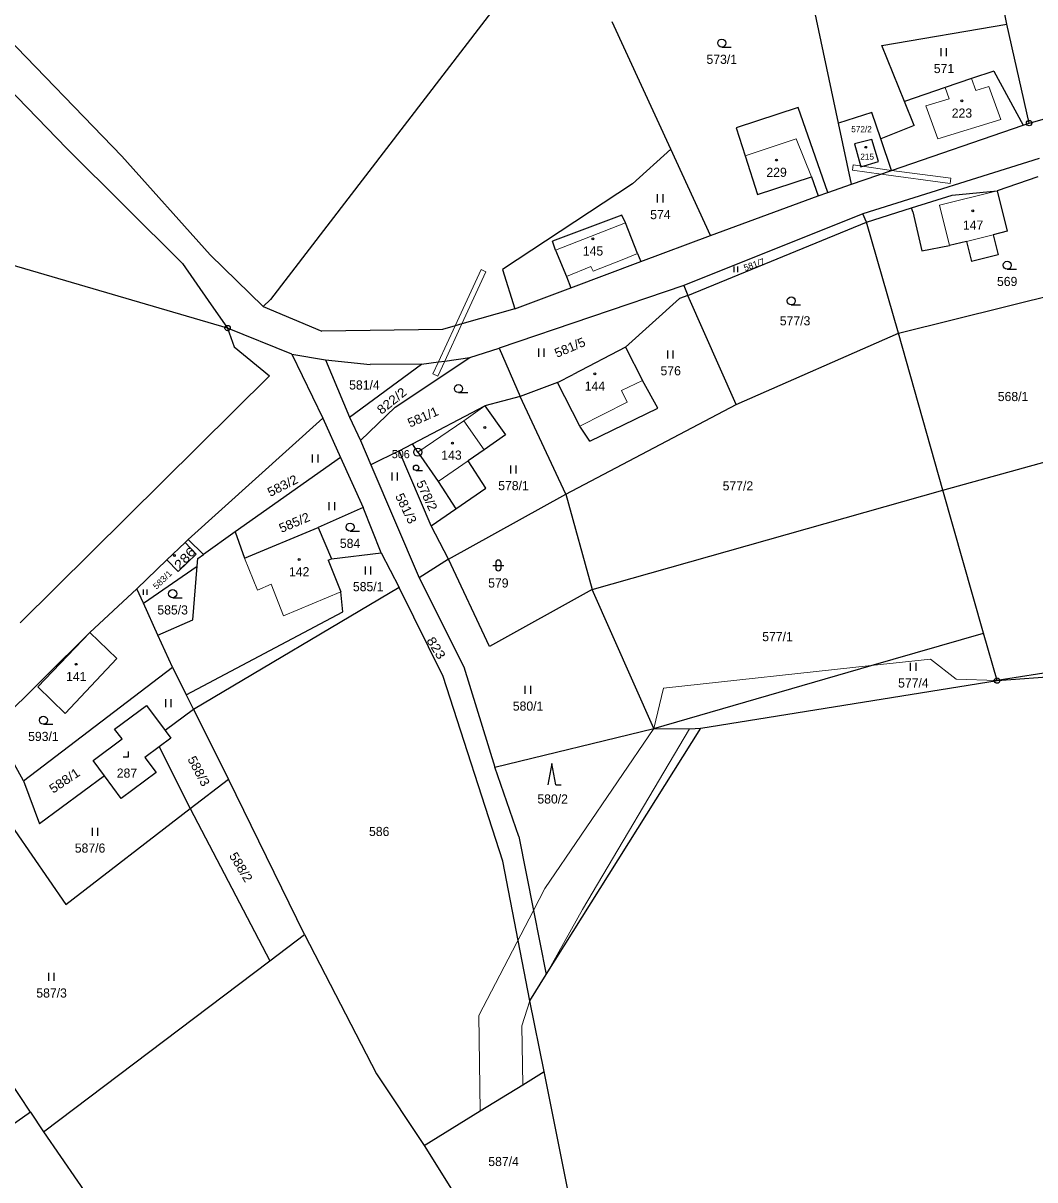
# Model space of a CAD drawing. Extents: x -739410 to -735662, y -942282 to -940043.
# Drawn here: x -737442.7 to -737254.3, y -941983.9 to -941768.5 of the extents above; entities that cross this region are included whole.
import ezdxf
from ezdxf.enums import TextEntityAlignment as Align

# ---------------------------------------------------------------- set-up
doc = ezdxf.new("R2010")
doc.units = 0
doc.header["$LTSCALE"] = 0.68
for name, color, linetype, lineweight in [('1', 7, 'Continuous', 25), ('13', 7, 'Continuous', 13), ('3', 7, 'Continuous', 25), ('4', 7, 'Continuous', 13), ('5', 7, 'Continuous', 25), ('8', 7, 'Continuous', 25)]:
    doc.layers.add(name, color=color, linetype=linetype, lineweight=lineweight)
doc.layers.add('2', color=7, linetype='Continuous')

msp = doc.modelspace()

# ---------------------------------------------------------------- linework, layer by layer
at = {"layer": '1'}
for p, q in [((-737495.33, -941729.23), (-737434.6, -941791.87)), ((-737424.35, -941793.26), (-737479, -941736.89)), ((-737259.53, -941768.73), (-737265.92, -941737.97)), ((-737290.93, -941787.13), (-737298.24, -941752.57)), ((-737348.36, -941757.03), (-737396.68, -941819.96)), ((-737322.15, -941791.96), (-737333.04, -941768.29)), ((-737282.81, -941772.69), (-737259.53, -941768.73)), ((-737255.41, -941787.13), (-737259.53, -941768.73)), ((-737278.63, -941783.09), (-737282.81, -941772.69)), ((-737266.13, -941778.85), (-737271.04, -941780.52)), ((-737261.99, -941777.45), (-737266.13, -941778.85)), ((-737261.99, -941777.45), (-737256.51, -941787.51)), ((-737271.04, -941780.52), (-737278.63, -941783.09)), ((-737255.41, -941787.13), (-737233.03, -941780.78)), ((-737276.83, -941787.56), (-737278.63, -941783.09)), ((-737298.43, -941784.23), (-737309.96, -941788.02)), ((-737292.89, -941800.03), (-737298.43, -941784.23)), ((-737284.7, -941785.15), (-737290.93, -941787.13)), ((-737283.03, -941790.07), (-737284.7, -941785.15)), ((-737288.51, -941798.52), (-737290.93, -941787.13)), ((-737276.83, -941787.56), (-737283.03, -941790.07)), ((-737281.03, -941795.94), (-737256.51, -941787.51)), ((-737256.51, -941787.51), (-737255.41, -941787.13)), ((-737309.96, -941788.02), (-737308.3, -941793.2)), ((-737434.6, -941791.87), (-737413.03, -941813.28)), ((-737322.15, -941791.96), (-737329.24, -941798.44)), ((-737314.76, -941808.04), (-737322.15, -941791.96)), ((-737284.7, -941790.18), (-737287.93, -941791.01)), ((-737287.93, -941791.01), (-737286.72, -941795.24)), ((-737283.45, -941794.25), (-737284.7, -941790.18)), ((-737407.91, -941811.64), (-737424.35, -941793.26)), ((-737286.72, -941795.24), (-737283.45, -941794.25)), ((-737253.55, -941793.72), (-737286.39, -941804.05)), ((-737329.24, -941798.44), (-737353.48, -941814.41)), ((-737295.96, -941797.12), (-737294.68, -941800.69)), ((-737292.89, -941800.03), (-737288.51, -941798.52)), ((-737253.77, -941797.16), (-737261.33, -941799.73)), ((-737314.76, -941808.04), (-737294.68, -941800.69)), ((-737294.68, -941800.69), (-737292.89, -941800.03)), ((-737277.3, -941802.91), (-737269.71, -941800.52)), ((-737269.71, -941800.52), (-737261.33, -941799.73)), ((-737261.33, -941799.73), (-737259.47, -941807.26)), ((-737285.71, -941805.56), (-737277.3, -941802.91)), ((-737277.08, -941803.67), (-737277.3, -941802.91)), ((-737404.65, -941825.3), (-737479.46, -941803.47)), ((-737331.25, -941804.25), (-737344.15, -941809.13)), ((-737330.59, -941805.73), (-737331.25, -941804.25)), ((-737286.39, -941804.05), (-737319.72, -941817.39)), ((-737277.08, -941803.67), (-737275.38, -941810.9)), ((-737328.31, -941811.43), (-737330.59, -941805.73)), ((-737279.75, -941826.24), (-737285.71, -941805.56)), ((-737259.47, -941807.26), (-737262.12, -941807.92)), ((-737343.61, -941810.76), (-737344.15, -941809.13)), ((-737327.7, -941812.89), (-737314.76, -941808.04)), ((-737267.08, -941809.17), (-737270.21, -941809.95)), ((-737267.08, -941809.17), (-737266.16, -941812.88)), ((-737262.12, -941807.92), (-737261.2, -941811.64)), ((-737343.61, -941810.76), (-737341.58, -941815.69)), ((-737328.31, -941811.43), (-737327.7, -941812.89)), ((-737275.38, -941810.9), (-737270.21, -941809.95)), ((-737413.03, -941813.28), (-737408.28, -941820.18)), ((-737398.04, -941821.29), (-737407.91, -941811.64)), ((-737340.74, -941817.78), (-737327.7, -941812.89)), ((-737261.2, -941811.64), (-737266.16, -941812.88)), ((-737353.48, -941814.41), (-737351.18, -941821.7)), ((-737341.58, -941815.69), (-737340.74, -941817.78)), ((-737279.75, -941826.24), (-737231.96, -941814.37)), ((-737319.72, -941817.39), (-737354.11, -941829.02)), ((-737351.18, -941821.7), (-737340.74, -941817.78)), ((-737319.72, -941817.39), (-737318.99, -941819.24)), ((-737408.28, -941820.18), (-737404.65, -941825.3)), ((-737396.68, -941819.96), (-737398.04, -941821.29)), ((-737320.54, -941819.8), (-737330.59, -941828.88)), ((-737318.99, -941819.24), (-737320.54, -941819.8)), ((-737309.99, -941839.56), (-737318.99, -941819.24)), ((-737398.04, -941821.29), (-737387.11, -941825.85)), ((-737392.69, -941830.17), (-737404.65, -941825.3)), ((-737404.65, -941825.3), (-737403.43, -941828.79)), ((-737364.65, -941825.57), (-737387.11, -941825.85)), ((-737309.99, -941839.56), (-737279.75, -941826.24)), ((-737271.48, -941855.47), (-737279.75, -941826.24)), ((-737403.43, -941828.79), (-737396.85, -941834.2)), ((-737392.69, -941830.17), (-737386.93, -941842.05)), ((-737392.69, -941830.17), (-737386.41, -941831.22)), ((-737373.44, -941840.02), (-737359.55, -941830.8)), ((-737359.55, -941830.8), (-737354.11, -941829.02)), ((-737354.11, -941829.02), (-737350.16, -941838.02)), ((-737330.59, -941828.88), (-737340.34, -941833.94)), ((-737330.59, -941828.88), (-737327.42, -941835.06)), ((-737386.41, -941831.22), (-737381.97, -941841.89)), ((-737386.41, -941831.22), (-737378.08, -941832.11)), ((-737381.97, -941841.89), (-737368.55, -941832.02)), ((-737368.55, -941832.02), (-737378.08, -941832.11)), ((-737443.31, -941880.17), (-737396.85, -941834.2)), ((-737343.23, -941835.46), (-737340.34, -941833.94)), ((-737324.55, -941840.21), (-737327.42, -941835.06)), ((-737343.23, -941835.46), (-737350.16, -941838.02)), ((-737339.09, -941843.56), (-737343.23, -941835.46)), ((-737350.16, -941838.02), (-737356.78, -941839.77)), ((-737341.65, -941856.22), (-737350.16, -941838.02)), ((-737341.65, -941856.22), (-737309.99, -941839.56)), ((-737379.88, -941846.25), (-737373.44, -941840.02)), ((-737370.21, -941846.83), (-737356.78, -941839.77)), ((-737356.78, -941839.77), (-737352.93, -941845.17)), ((-737337.22, -941846.33), (-737324.55, -941840.21)), ((-737386.93, -941842.05), (-737412.02, -941864.69)), ((-737386.93, -941842.05), (-737383.61, -941849.43)), ((-737381.97, -941841.89), (-737379.88, -941846.25)), ((-737337.22, -941846.33), (-737339.09, -941843.56)), ((-737271.48, -941855.47), (-737224.06, -941842.41)), ((-737352.93, -941845.17), (-737356.88, -941847.98)), ((-737379.88, -941846.25), (-737377.97, -941850.74)), ((-737372.73, -941848.16), (-737377.97, -941850.74)), ((-737372.73, -941848.16), (-737370.21, -941846.83)), ((-737366.77, -941862.11), (-737372.73, -941848.16)), ((-737369.22, -941848.38), (-737370.21, -941846.83)), ((-737356.88, -941847.98), (-737359.86, -941850.04)), ((-737383.61, -941849.43), (-737403.26, -941863.27)), ((-737383.61, -941849.43), (-737379.42, -941858.72)), ((-737369.22, -941848.38), (-737365.43, -941853.89)), ((-737356.55, -941855.11), (-737359.86, -941850.04)), ((-737377.97, -941850.74), (-737368.98, -941871.82)), ((-737365.43, -941853.89), (-737362.14, -941858.94)), ((-737363.54, -941868.34), (-737341.65, -941856.22)), ((-737362.14, -941858.94), (-737356.55, -941855.11)), ((-737341.65, -941856.22), (-737336.76, -941874.01)), ((-737336.76, -941874.01), (-737271.48, -941855.47)), ((-737263.89, -941882.1), (-737271.48, -941855.47)), ((-737379.42, -941858.72), (-737387.78, -941862.43)), ((-737376.08, -941867.16), (-737379.42, -941858.72)), ((-737366.77, -941862.11), (-737362.14, -941858.94)), ((-737403.26, -941863.27), (-737409.17, -941867.45)), ((-737403.26, -941863.27), (-737401.48, -941868.16)), ((-737401.48, -941868.16), (-737387.78, -941862.43)), ((-737387.78, -941862.43), (-737385.29, -941868.27)), ((-737363.54, -941868.34), (-737366.77, -941862.11)), ((-737412.54, -941865.25), (-737415.95, -941868.48)), ((-737412.02, -941864.69), (-737412.54, -941865.25)), ((-737410.48, -941867.43), (-737412.54, -941865.25)), ((-737409.17, -941867.45), (-737412.02, -941864.69)), ((-737413.89, -941870.66), (-737410.48, -941867.43)), ((-737385.29, -941868.27), (-737376.08, -941867.16)), ((-737376.08, -941867.16), (-737372.7, -941873.6)), ((-737415.95, -941868.48), (-737421.58, -941873.83)), ((-737420.34, -941876.55), (-737410.33, -941869.65)), ((-737415.95, -941868.48), (-737413.89, -941870.66)), ((-737411.16, -941879.61), (-737410.33, -941869.65)), ((-737385.92, -941868.5), (-737385.29, -941868.27)), ((-737385.92, -941868.5), (-737383.57, -941874.4)), ((-737363.54, -941868.34), (-737368.98, -941871.82)), ((-737355.87, -941884.57), (-737363.54, -941868.34)), ((-737368.98, -941871.82), (-737360.65, -941888.37)), ((-737421.58, -941873.83), (-737430.33, -941882)), ((-737420.34, -941876.55), (-737421.58, -941873.83)), ((-737372.7, -941873.6), (-737410.99, -941896.33)), ((-737364.49, -941890.18), (-737372.7, -941873.6)), ((-737336.76, -941874.01), (-737355.87, -941884.57)), ((-737325.32, -941899.84), (-737336.76, -941874.01)), ((-737417.63, -941882.47), (-737420.34, -941876.55)), ((-737417.63, -941882.47), (-737411.16, -941879.61)), ((-737430.33, -941882), (-737448.15, -941899.68)), ((-737430.33, -941882), (-737439.99, -941892.12)), ((-737425.28, -941886.86), (-737430.33, -941882)), ((-737414.9, -941888.44), (-737417.63, -941882.47)), ((-737261.37, -941890.95), (-737263.89, -941882.1)), ((-737212.83, -941883.15), (-737261.37, -941890.95)), ((-737434.93, -941897.07), (-737425.28, -941886.86)), ((-737442.65, -941909.6), (-737414.9, -941888.44)), ((-737414.9, -941888.44), (-737412.35, -941893.59)), ((-737360.65, -941888.37), (-737354.87, -941907.07)), ((-737261.37, -941890.95), (-737228.67, -941888.55)), ((-737353.38, -941924.6), (-737364.49, -941890.18)), ((-737316.55, -941899.8), (-737261.37, -941890.95)), ((-737439.99, -941892.12), (-737434.93, -941897.07)), ((-737425.69, -941899.97), (-737419.74, -941895.56)), ((-737419.74, -941895.56), (-737416.27, -941900.25)), ((-737412.35, -941893.59), (-737410.99, -941896.33)), ((-737410.99, -941896.33), (-737416.27, -941900.25)), ((-737410.99, -941896.33), (-737404.49, -941909.29)), ((-737442.65, -941909.6), (-737448.15, -941899.68)), ((-737354.87, -941907.07), (-737325.32, -941899.84)), ((-737345.32, -941945.69), (-737316.55, -941899.8)), ((-737429.7, -941905.81), (-737424.32, -941901.82)), ((-737424.32, -941901.82), (-737425.69, -941899.97)), ((-737415.22, -941901.67), (-737417.42, -941903.31)), ((-737416.27, -941900.25), (-737415.22, -941901.67)), ((-737417.42, -941903.31), (-737420.07, -941905.28)), ((-737417.42, -941903.31), (-737411.62, -941914.78)), ((-737453.79, -941905.27), (-737434.79, -941932.62)), ((-737427.6, -941908.67), (-737429.7, -941905.81)), ((-737420.07, -941905.28), (-737417.98, -941908.09)), ((-737417.98, -941908.09), (-737424.48, -941912.92)), ((-737350.43, -941919.96), (-737354.87, -941907.07)), ((-737442.65, -941909.6), (-737439.68, -941917.64)), ((-737427.6, -941908.67), (-737439.68, -941917.64)), ((-737424.48, -941912.92), (-737427.6, -941908.67)), ((-737411.62, -941914.78), (-737404.49, -941909.29)), ((-737390.35, -941938.25), (-737404.49, -941909.29)), ((-737434.79, -941932.62), (-737411.62, -941914.78)), ((-737411.62, -941914.78), (-737396.8, -941943.13)), ((-737348.39, -941950.58), (-737353.38, -941924.6)), ((-737396.8, -941943.13), (-737390.35, -941938.25)), ((-737390.35, -941938.25), (-737376.93, -941964.2)), ((-737438.91, -941974.95), (-737396.8, -941943.13)), ((-737348.39, -941950.58), (-737345.32, -941945.69)), ((-737345.73, -941963.76), (-737348.39, -941950.58)), ((-737441.36, -941971.32), (-737448.27, -941960.89)), ((-737376.93, -941964.2), (-737368.03, -941977.51)), ((-737340.98, -941987.35), (-737345.73, -941963.76)), ((-737441.36, -941971.32), (-737473.24, -941993.67)), ((-737441.36, -941971.32), (-737438.91, -941974.95)), ((-737438.91, -941974.95), (-737423.49, -941997.32))]:
    msp.add_line(p, q, dxfattribs=at)
for points in [[(-737288.51, -941798.52), (-737281.03, -941795.94), (-737283.03, -941790.07)], [(-737308.3, -941793.2), (-737305.97, -941800.44), (-737295.96, -941797.12)], [(-737318.99, -941819.24), (-737285.71, -941805.56), (-737286.39, -941804.05)], [(-737351.18, -941821.7), (-737361.03, -941824.53), (-737362.29, -941824.89), (-737364.65, -941825.57)], [(-737368.55, -941832.02), (-737365.39, -941831.59), (-737364.22, -941831.43), (-737359.55, -941830.8)], [(-737410.33, -941869.65), (-737410.21, -941868.19), (-737409.17, -941867.45)], [(-737412.35, -941893.59), (-737383.19, -941878.15), (-737383.57, -941874.4)], [(-737325.32, -941899.84), (-737284.83, -941888.15), (-737263.89, -941882.1)], [(-737325.32, -941899.84), (-737318.66, -941899.9), (-737316.55, -941899.8)], [(-737350.43, -941919.96), (-737347.69, -941933.75), (-737345.32, -941945.69)], [(-737368.03, -941977.51), (-737357.61, -941971.09), (-737349.68, -941966.2), (-737345.73, -941963.76)], [(-737368.03, -941977.51), (-737357.23, -941994.79), (-737356.28, -941996.51)]]:
    msp.add_lwpolyline(points, dxfattribs=at)
at = {"layer": '13'}
for points in [[(-737281.03, -941795.94), (-737288.16, -941794.89), (-737288.29, -941795.88), (-737282.97, -941796.61)], [(-737270.01, -941797.38), (-737281.03, -941795.94), (-737282.97, -941796.61), (-737270.14, -941798.37)], [(-737356.55, -941814.84), (-737357.45, -941814.42), (-737362.29, -941824.89), (-737361.03, -941824.53)], [(-737362.29, -941824.89), (-737365.39, -941831.59), (-737364.22, -941831.43), (-737361.03, -941824.53)], [(-737365.39, -941831.59), (-737366.43, -941833.84), (-737365.53, -941834.26), (-737364.22, -941831.43)], [(-737261.37, -941890.95), (-737269.01, -941890.7), (-737273.76, -941886.94), (-737284.83, -941888.15), (-737325.32, -941899.84), (-737318.66, -941899.9), (-737316.55, -941899.8)], [(-737284.83, -941888.15), (-737323.48, -941892.36), (-737325.32, -941899.84)], [(-737345.57, -941929.68), (-737347.69, -941933.75), (-737345.32, -941945.69), (-737338.57, -941933.56), (-737318.66, -941899.9), (-737325.32, -941899.84)], [(-737357.9, -941953.32), (-737357.61, -941971.09), (-737349.68, -941966.2), (-737349.86, -941955.22), (-737348.39, -941950.58), (-737345.32, -941945.69), (-737347.69, -941933.75)]]:
    msp.add_lwpolyline(points, close=True, dxfattribs=at)
at = {"layer": '3'}
for p, q in [((-737312.633, -941772.97), (-737310.883, -941772.97)), ((-737271.771, -941774.69), (-737271.771, -941773.19)), ((-737270.77, -941774.69), (-737270.77, -941773.19)), ((-737324.581, -941801.89), (-737324.581, -941800.39)), ((-737323.58, -941801.89), (-737323.58, -941800.39)), ((-737310.358, -941814.91), (-737310.358, -941813.86)), ((-737309.657, -941814.91), (-737309.657, -941813.86)), ((-737259.493, -941814.34), (-737257.743, -941814.34)), ((-737299.703, -941820.98), (-737297.953, -941820.98)), ((-737346.681, -941830.63), (-737346.681, -941829.13)), ((-737345.68, -941830.63), (-737345.68, -941829.13)), ((-737322.661, -941830.97), (-737322.661, -941829.47)), ((-737321.66, -941830.97), (-737321.66, -941829.47)), ((-737361.663, -941837.32), (-737359.913, -941837.32)), ((-737388.821, -941850.33), (-737388.821, -941848.83)), ((-737387.82, -941850.33), (-737387.82, -941848.83)), ((-737374.021, -941853.69), (-737374.021, -941852.19)), ((-737373.02, -941853.69), (-737373.02, -941852.19)), ((-737369.555, -941851.82), (-737368.383, -941851.82)), ((-737351.931, -941852.36), (-737351.931, -941850.86)), ((-737350.93, -941852.36), (-737350.93, -941850.86)), ((-737385.721, -941859.2), (-737385.721, -941857.7)), ((-737384.72, -941859.2), (-737384.72, -941857.7)), ((-737381.853, -941863.12), (-737380.103, -941863.12)), ((-737378.991, -941871.18), (-737378.991, -941869.68)), ((-737377.99, -941871.18), (-737377.99, -941869.68)), ((-737355.241, -941869.501), (-737353.239, -941869.501)), ((-737354.741, -941869.001), (-737354.741, -941870.002)), ((-737353.739, -941870.002), (-737353.739, -941869.001)), ((-737420.292, -941874.99), (-737420.292, -941873.985)), ((-737419.622, -941874.99), (-737419.622, -941873.985)), ((-737414.883, -941875.51), (-737413.133, -941875.51)), ((-737277.471, -941889.12), (-737277.471, -941887.62)), ((-737276.47, -941889.12), (-737276.47, -941887.62)), ((-737349.221, -941893.42), (-737349.221, -941891.92)), ((-737348.22, -941893.42), (-737348.22, -941891.92)), ((-737416.151, -941895.89), (-737416.151, -941894.39)), ((-737415.15, -941895.89), (-737415.15, -941894.39)), ((-737438.953, -941899.07), (-737437.203, -941899.07)), ((-737343.53, -941910.38), (-737342.534, -941910.38)), ((-737429.811, -941919.86), (-737429.811, -941918.36)), ((-737428.81, -941919.86), (-737428.81, -941918.36)), ((-737437.941, -941946.85), (-737437.941, -941945.35)), ((-737436.94, -941946.85), (-737436.94, -941945.35))]:
    msp.add_line(p, q, dxfattribs=at)
for points in [[(-737424.081, -941905.13), (-737423.08, -941905.13), (-737423.08, -941904.13)], [(-737343.53, -941910.38), (-737344.28, -941906.38), (-737345.03, -941910.38)]]:
    msp.add_lwpolyline(points, dxfattribs=at)
for centre, radius in [((-737312.6329, -941772.2198), 0.75), ((-737259.4929, -941813.5898), 0.75), ((-737299.7029, -941820.2298), 0.75), ((-737361.6629, -941836.5698), 0.75), ((-737369.5552, -941851.3174), 0.5025), ((-737381.8529, -941862.3698), 0.75), ((-737414.8829, -941874.7598), 0.75), ((-737438.9529, -941898.3198), 0.75)]:
    msp.add_circle(centre, radius, dxfattribs=at)
for centre, start, end in [((-737354.24, -941869.0009), 0, 180), ((-737354.24, -941870.0009), 180, 359.98789)]:
    msp.add_arc(centre, 0.5, start, end, dxfattribs=at)
at = {"layer": '4'}
for p, q in [((-737265.33, -941781.07), (-737266.13, -941778.85)), ((-737270.29, -941782.6), (-737271.04, -941780.52)), ((-737262.9, -941780.32), (-737265.33, -941781.07)), ((-737260.67, -941786.46), (-737262.9, -941780.32)), ((-737270.29, -941782.6), (-737274.66, -941783.94)), ((-737272.43, -941790.08), (-737274.66, -941783.94)), ((-737260.67, -941786.46), (-737272.43, -941790.08)), ((-737261.33, -941799.73), (-737272.07, -941802.42)), ((-737272.07, -941802.42), (-737270.21, -941809.95)), ((-737330.59, -941805.73), (-737343.61, -941810.76)), ((-737262.12, -941807.92), (-737267.08, -941809.17)), ((-737330.87, -941812.45), (-737328.31, -941811.43)), ((-737336.6, -941814.69), (-737330.87, -941812.45)), ((-737341.58, -941815.69), (-737337.01, -941813.84)), ((-737337.01, -941813.84), (-737336.6, -941814.69)), ((-737327.42, -941835.06), (-737331.33, -941836.94)), ((-737331.33, -941836.94), (-737330.23, -941839.09)), ((-737339.09, -941843.56), (-737330.23, -941839.09)), ((-737356.78, -941839.77), (-737360.7, -941842.56)), ((-737359.86, -941850.04), (-737365.43, -941853.89)), ((-737401.48, -941868.16), (-737399.12, -941874.08)), ((-737396.57, -941873.01), (-737399.12, -941874.08)), ((-737396.57, -941873.01), (-737394.27, -941878.89)), ((-737383.57, -941874.4), (-737394.27, -941878.89))]:
    msp.add_line(p, q, dxfattribs=at)
for points in [[(-737308.3, -941793.2), (-737298.8, -941790.05), (-737295.96, -941797.12)], [(-737369.22, -941848.38), (-737360.7, -941842.56), (-737356.88, -941847.98)]]:
    msp.add_lwpolyline(points, dxfattribs=at)
at = {"layer": '5'}
for centre in [(-737267.9268, -941782.9892), (-737285.8368, -941791.6292), (-737302.4368, -941794.0092), (-737265.9168, -941803.4692), (-737336.6268, -941808.6692), (-737336.2768, -941833.8292), (-737356.7668, -941843.7992), (-737362.8068, -941846.7392), (-737414.5668, -941867.6492), (-737391.3368, -941868.3992), (-737432.8468, -941887.9092)]:
    msp.add_circle(centre, 0.175, dxfattribs=at)
at = {"layer": '8'}
for centre, radius in [((-737255.41, -941787.1299), 0.5), ((-737255.41, -941787.1299), 0.0303), ((-737404.65, -941825.2999), 0.5), ((-737404.65, -941825.2999), 0.0303), ((-737369.24, -941848.4098), 0.75), ((-737369.24, -941848.4098), 0.03), ((-737261.37, -941890.9499), 0.5), ((-737261.37, -941890.9499), 0.0303)]:
    msp.add_circle(centre, radius, dxfattribs=at)

# ---------------------------------------------------------------- texts
at = {"layer": '2'}
for s, height, p in [('573/1', 1.7, (-737312.64, -941776.095)), ('571', 1.7, (-737271.259, -941777.815)), ('223', 1.7, (-737267.919, -941786.115)), ('572/2', 1.14, (-737286.619, -941788.825)), ('215', 1.14, (-737285.57, -941793.945)), ('229', 1.7, (-737302.429, -941797.135)), ('574', 1.7, (-737324.069, -941805.015)), ('147', 1.7, (-737265.839, -941806.965)), ('145', 1.7, (-737336.619, -941811.795)), ('569', 1.7, (-737259.499, -941817.465)), ('577/3', 1.7, (-737298.99, -941824.795)), ('576', 1.7, (-737322.149, -941834.095)), ('581/4', 1.7, (-737379.18, -941836.745)), ('144', 1.7, (-737336.269, -941836.955)), ('568/1', 1.7, (-737258.4, -941838.895)), ('143', 1.7, (-737362.969, -941849.805)), ('578/1', 1.7, (-737351.42, -941855.485)), ('577/2', 1.7, (-737309.63, -941855.525)), ('584', 1.7, (-737381.859, -941866.245)), ('142', 1.7, (-737391.329, -941871.525)), ('579', 1.7, (-737354.239, -941873.625)), ('585/1', 1.7, (-737378.48, -941874.305)), ('585/3', 1.7, (-737414.89, -941878.635)), ('577/1', 1.7, (-737302.26, -941883.605)), ('141', 1.7, (-737432.839, -941891.035)), ('577/4', 1.7, (-737276.96, -941892.245)), ('580/1', 1.7, (-737348.71, -941896.545)), ('593/1', 1.7, (-737438.96, -941902.195)), ('287', 1.7, (-737423.399, -941909.025)), ('580/2', 1.7, (-737344.13, -941913.845)), ('586', 1.7, (-737376.429, -941919.895)), ('587/6', 1.7, (-737430.27, -941922.985)), ('587/3', 1.7, (-737437.43, -941949.975)), ('587/4', 1.7, (-737353.27, -941981.355))]:
    msp.add_text(s, height=height, dxfattribs=at).set_placement(p, align=Align.CENTER)
msp.add_text('581/7', height=1.2, rotation=19, dxfattribs=at).set_placement((-737306.4123, -941814.0489), align=Align.CENTER)
for s, height, rotation, width, p in [('581/5', 1.7, 23, 1.05, (-737340.5841, -941829.689)), ('822/2', 1.7, 39, 1.1, (-737373.5594, -941839.5095)), ('581/1', 1.7, 24, 1.05, (-737367.9407, -941842.6389)), ('583/2', 1.7, 27, 1.05, (-737394.0304, -941855.4083)), ('578/2', 1.7, 295, 1.05, (-737368.3191, -941856.8323)), ('581/3', 1.7, 296, 1.05, (-737372.1894, -941859.2554)), ('585/2', 1.7, 23, 1.05, (-737391.8941, -941862.299)), ('286', 1.7, 47, 1.2, (-737411.993, -941868.7337)), ('583/1', 1.14, 44, 1.1, (-737416.3905, -941872.5803)), ('823', 1.7, 302, 1.15, (-737366.5466, -941885.3241)), ('588/3', 1.7, 298, 1.05, (-737410.7764, -941908.2024)), ('588/1', 1.7, 34, 1.1, (-737434.5598, -941910.2789)), ('588/2', 1.7, 301, 1.05, (-737402.8995, -941926.1207))]:
    msp.add_text(s, height=height, rotation=rotation, dxfattribs=dict(at, width=width)).set_placement(p, align=Align.CENTER)
at = {"layer": '8'}
msp.add_text('506', height=1.5, dxfattribs=at).set_placement((-737370.739, -941849.527), align=Align.RIGHT)

doc.saveas('drawing.dxf')
